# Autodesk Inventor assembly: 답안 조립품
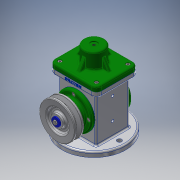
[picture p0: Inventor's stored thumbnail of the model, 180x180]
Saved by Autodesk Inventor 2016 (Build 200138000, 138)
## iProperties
Created: 2018-10
Part Number: 답안 조립품
Material: 일반
Document SubType Name: Assembly
Designer: 3sil_cad019
Author: 3sil_cad019
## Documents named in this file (18)
- C:\Users\3sil_cad019\Desktop\481008V1005\답안 조립품.iam
- C:\Users\3sil_cad019\Desktop\481008V1005\본체.ipt
- C:\Users\3sil_cad019\Desktop\481008V1005\V-벨트풀리.ipt
- C:\Users\3sil_cad019\Desktop\481008V1005\E-링.ipt
- C:\Users\3sil_cad019\Desktop\481008V1005\베어링 17 x 40 x 12.ipt
- C:\Users\3sil_cad019\Desktop\481008V1005\덮개.ipt
- C:\Users\3sil_cad019\Desktop\481008V1005\뒤커버.ipt
- C:\Users\3sil_cad019\Desktop\481008V1005\링크.ipt
- C:\Users\3sil_cad019\Desktop\481008V1005\앞커버.ipt
- C:\Users\3sil_cad019\Desktop\481008V1005\오일 실 17 30 8.ipt
- C:\Users\3sil_cad019\Desktop\481008V1005\와셔 4x16.ipt
- C:\Users\3sil_cad019\Desktop\481008V1005\클레비스 핀 6 x 22.ipt
- 클레비스 핀 6 x 22.ipt
- C:\Users\3sil_cad019\Desktop\481008V1005\키 4 x 4 x 12.ipt
- C:\Users\3sil_cad019\Desktop\481008V1005\편심축.ipt
- C:\Users\3sil_cad019\Desktop\481008V1005\볼트 M4 x 8.ipt
- C:\Users\3sil_cad019\Desktop\481008V1005\볼트 M4 x 10.ipt
- C:\Users\3sil_cad019\Desktop\481008V1005\슬라이더.ipt
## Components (2 placed, 2 different names)
1. V-벨트풀리:1
2. E-링:1 — 각도:2
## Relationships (1: Angle 1)
- 각도:2 [Angle]: E-링:1
